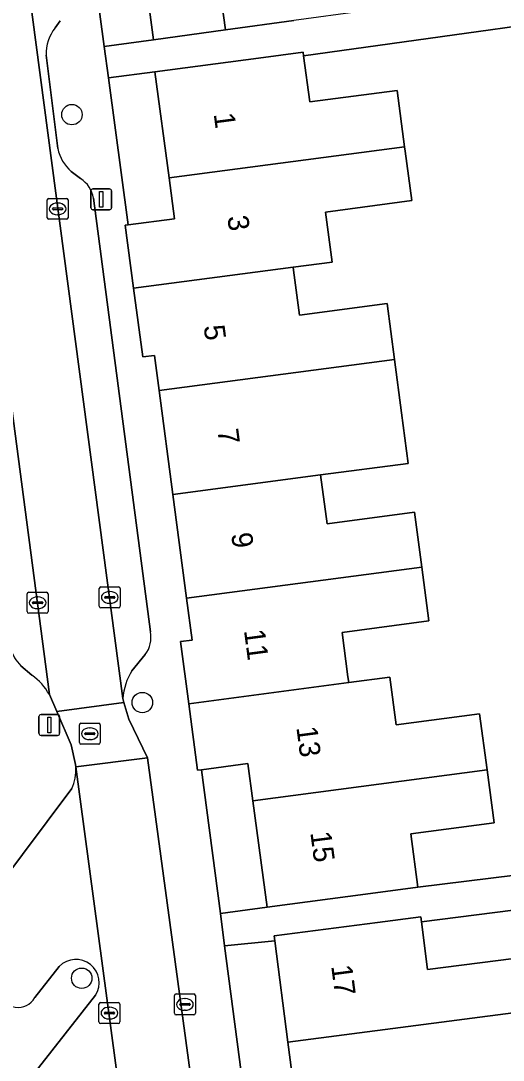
# Model space of a CAD drawing. Extents: x 163147 to 163550, y 380933 to 381639.
# Drawn here: x 163326.27 to 163349.36, y 381413.54 to 381463.34 of the extents above; entities that cross this region are included whole.
import ezdxf

# ---------------------------------------------------------------- set-up
doc = ezdxf.new("R2010")
doc.units = 0
for name, color, linetype in [('IMGEO_Boom', 7, 'Continuous'), ('IMGEO_Erf', 7, 'Continuous'), ('IMGEO_Kolk', 7, 'Continuous'), ('IMGEO_Lichtmast', 7, 'Continuous'), ('IMGEO_Pand', 7, 'Continuous'), ('IMGEO_Pand_nummerreeks', 7, 'Continuous'), ('IMGEO_Parkeervlak_open', 7, 'Continuous'), ('IMGEO_Rijbaan_lokaal_open', 7, 'Continuous'), ('IMGEO_Rioolput', 7, 'Continuous'), ('IMGEO_Voetpad_open', 7, 'Continuous')]:
    doc.layers.add(name, color=color, linetype=linetype)

msp = doc.modelspace()

# ---------------------------------------------------------------- linework, layer by layer
at = {"layer": 'IMGEO_Boom'}
for centre in [(163328.72, 381458.839), (163332.089, 381430.675), (163329.187, 381417.469)]:
    msp.add_circle(centre, 0.489, dxfattribs=at)
at = {"layer": 'IMGEO_Erf'}
for points in [[(163327.51, 381482.721), (163330.269, 381462.107), (163332.631, 381462.423), (163332.25, 381465.197)], [(163335.686, 381465.67), (163336.067, 381462.896), (163339.339, 381463.347)], [(163358.388, 381464.242), (163339.808, 381461.652), (163340.1, 381459.446), (163344.282, 381460), (163344.64, 381457.298), (163344.668, 381457.09), (163344.982, 381454.719), (163340.863, 381454.173), (163341.181, 381451.778), (163339.303, 381451.53), (163339.322, 381451.385), (163339.607, 381449.237), (163343.805, 381449.793), (163344.16, 381447.11), (163344.498, 381444.558), (163344.819, 381442.134), (163340.621, 381441.579), (163340.931, 381439.239), (163345.113, 381439.793), (163345.462, 381437.157), (163345.803, 381434.582), (163341.649, 381434.032), (163341.93, 381431.91), (163341.967, 381431.632), (163343.93, 381431.892), (163344.231, 381429.611), (163348.23, 381430.14), (163348.587, 381427.446), (163348.922, 381424.915), (163344.932, 381424.387), (163345.271, 381421.825), (163364.034, 381424.153)], [(163365.447, 381412.799), (163365.299, 381413.897), (163365.397, 381413.911), (163365.319, 381414.45), (163361.948, 381413.958), (163361.457, 381417.324), (163360.95, 381420.808), (163364.321, 381421.299), (163364.137, 381422.557), (163345.444, 381420.177), (163345.743, 381417.879), (163349.875, 381418.417), (163350.208, 381415.86), (163350.548, 381413.245)]]:
    msp.add_lwpolyline(points, dxfattribs=at)
for points in [[(163332.691, 381460.898), (163330.47, 381460.601), (163331.412, 381453.563), (163333.624, 381453.855), (163333.366, 381455.806)], [(163337.382, 381425.964), (163337.146, 381427.749), (163334.918, 381427.453), (163335.823, 381420.576), (163338.057, 381420.87)], [(163341.643, 381394.54), (163340.996, 381399.507), (163340.35, 381404.474), (163339.703, 381409.442), (163339.057, 381414.409), (163338.425, 381419.264), (163336.029, 381419.012), (163342.573, 381369.282), (163344.89, 381369.587), (163344.228, 381374.671), (163343.582, 381379.638), (163342.936, 381384.606), (163342.289, 381389.573)]]:
    msp.add_lwpolyline(points, close=True, dxfattribs=at)
at = {"layer": 'IMGEO_Kolk'}
for p, q in [((163327.536, 381453.899), (163327.536, 381454.751)), ((163327.611, 381454.825), (163328.463, 381454.825)), ((163328.024, 381454.605), (163328.049, 381454.605)), ((163328.537, 381454.751), (163328.537, 381453.899)), ((163327.795, 381454.319), (163327.795, 381454.331)), ((163328.233, 381454.282), (163327.835, 381454.282)), ((163327.838, 381454.368), (163328.236, 381454.368)), ((163328.047, 381454.045), (163328.022, 381454.045)), ((163328.279, 381454.331), (163328.279, 381454.319)), ((163328.463, 381453.825), (163327.611, 381453.825)), ((163326.653, 381435.956), (163327.505, 381435.956)), ((163330.028, 381435.285), (163330.028, 381436.137)), ((163330.103, 381436.211), (163330.955, 381436.211)), ((163330.516, 381435.991), (163330.541, 381435.991)), ((163331.029, 381436.137), (163331.029, 381435.285)), ((163326.578, 381435.03), (163326.578, 381435.882)), ((163326.837, 381435.45), (163326.837, 381435.462)), ((163326.88, 381435.499), (163327.278, 381435.499)), ((163327.066, 381435.736), (163327.091, 381435.736)), ((163327.321, 381435.462), (163327.321, 381435.45)), ((163327.579, 381435.882), (163327.579, 381435.03)), ((163330.287, 381435.705), (163330.287, 381435.717)), ((163330.725, 381435.668), (163330.327, 381435.668)), ((163330.33, 381435.754), (163330.728, 381435.754)), ((163330.771, 381435.717), (163330.771, 381435.705)), ((163327.275, 381435.413), (163326.877, 381435.413)), ((163327.089, 381435.176), (163327.064, 381435.176)), ((163330.955, 381435.211), (163330.103, 381435.211)), ((163330.539, 381435.431), (163330.514, 381435.431)), ((163327.505, 381434.956), (163326.653, 381434.956)), ((163333.628, 381415.788), (163333.628, 381416.64)), ((163333.703, 381416.714), (163334.555, 381416.714)), ((163334.629, 381416.64), (163334.629, 381415.788)), ((163330.012, 381415.373), (163330.012, 381416.225)), ((163330.087, 381416.299), (163330.939, 381416.299)), ((163330.5, 381416.079), (163330.525, 381416.079)), ((163331.013, 381416.225), (163331.013, 381415.373)), ((163333.887, 381416.208), (163333.887, 381416.22)), ((163334.325, 381416.171), (163333.927, 381416.171)), ((163333.93, 381416.257), (163334.328, 381416.257)), ((163334.116, 381416.494), (163334.141, 381416.494)), ((163334.371, 381416.22), (163334.371, 381416.208)), ((163330.271, 381415.793), (163330.271, 381415.805)), ((163330.709, 381415.756), (163330.311, 381415.756)), ((163330.314, 381415.842), (163330.712, 381415.842)), ((163330.755, 381415.805), (163330.755, 381415.793)), ((163334.555, 381415.714), (163333.703, 381415.714)), ((163334.139, 381415.934), (163334.114, 381415.934)), ((163330.939, 381415.299), (163330.087, 381415.299)), ((163330.523, 381415.519), (163330.498, 381415.519))]:
    msp.add_line(p, q, dxfattribs=at)
for points in [[(163327.536, 381453.899), (163327.536, 381454.751)], [(163327.611, 381454.825), (163328.463, 381454.825)], [(163328.537, 381454.751), (163328.537, 381453.899)], [(163328.463, 381453.825), (163327.611, 381453.825)], [(163326.653, 381435.956), (163327.505, 381435.956)], [(163330.028, 381435.285), (163330.028, 381436.137)], [(163330.103, 381436.211), (163330.955, 381436.211)], [(163331.029, 381436.137), (163331.029, 381435.285)], [(163326.578, 381435.03), (163326.578, 381435.882)], [(163327.579, 381435.882), (163327.579, 381435.03)], [(163330.955, 381435.211), (163330.103, 381435.211)], [(163327.505, 381434.956), (163326.653, 381434.956)], [(163333.628, 381415.788), (163333.628, 381416.64)], [(163333.703, 381416.714), (163334.555, 381416.714)], [(163334.629, 381416.64), (163334.629, 381415.788)], [(163330.012, 381415.373), (163330.012, 381416.225)], [(163330.087, 381416.299), (163330.939, 381416.299)], [(163331.013, 381416.225), (163331.013, 381415.373)], [(163334.555, 381415.714), (163333.703, 381415.714)], [(163330.939, 381415.299), (163330.087, 381415.299)]]:
    msp.add_lwpolyline(points, dxfattribs=at)
for centre, radius, start, end in [((163327.613, 381454.749), 0.0765, 91.552, 178.448), ((163327.613, 381454.749), 0.0765, 91.552, 178.448), ((163328.461, 381454.749), 0.0765, 1.552, 88.448), ((163328.461, 381454.749), 0.0765, 1.552, 88.448), ((163327.613, 381453.901), 0.0765, 181.552, 268.448), ((163327.613, 381453.901), 0.0765, 181.552, 268.448), ((163327.835, 381454.328), 0.0403, 85.8775, 175.7526), ((163327.832, 381454.318), 0.0366, 178.938, 274.7102), ((163328.236, 381454.325), 0.043, 264.8664, 352.4533), ((163328.24, 381454.33), 0.0386, 1.7309, 96.639), ((163328.461, 381453.901), 0.0765, 271.552, 358.448), ((163328.461, 381453.901), 0.0765, 271.552, 358.448), ((163326.655, 381435.88), 0.0765, 91.552, 178.448), ((163326.655, 381435.88), 0.0765, 91.552, 178.448), ((163327.503, 381435.88), 0.0765, 1.552, 88.448), ((163327.503, 381435.88), 0.0765, 1.552, 88.448), ((163330.105, 381436.135), 0.0765, 91.552, 178.448), ((163330.105, 381436.135), 0.0765, 91.552, 178.448), ((163330.953, 381436.135), 0.0765, 1.552, 88.448), ((163330.953, 381436.135), 0.0765, 1.552, 88.448), ((163326.877, 381435.459), 0.0403, 85.8775, 175.7526), ((163327.282, 381435.461), 0.0386, 1.7309, 96.639), ((163330.327, 381435.714), 0.0403, 85.8775, 175.7526), ((163330.324, 381435.704), 0.0366, 178.938, 274.7102), ((163330.728, 381435.711), 0.043, 264.8664, 352.4533), ((163330.732, 381435.716), 0.0386, 1.7309, 96.639), ((163326.655, 381435.032), 0.0765, 181.552, 268.448), ((163326.655, 381435.032), 0.0765, 181.552, 268.448), ((163326.874, 381435.449), 0.0366, 178.938, 274.7102), ((163327.278, 381435.456), 0.043, 264.8664, 352.4533), ((163327.503, 381435.032), 0.0765, 271.552, 358.448), ((163327.503, 381435.032), 0.0765, 271.552, 358.448), ((163330.105, 381435.287), 0.0765, 181.552, 268.448), ((163330.105, 381435.287), 0.0765, 181.552, 268.448), ((163330.953, 381435.287), 0.0765, 271.552, 358.448), ((163330.953, 381435.287), 0.0765, 271.552, 358.448), ((163333.705, 381416.638), 0.0765, 91.552, 178.448), ((163333.705, 381416.638), 0.0765, 91.552, 178.448), ((163334.553, 381416.638), 0.0765, 1.552, 88.448), ((163334.553, 381416.638), 0.0765, 1.552, 88.448), ((163330.089, 381416.223), 0.0765, 91.552, 178.448), ((163330.089, 381416.223), 0.0765, 91.552, 178.448), ((163330.937, 381416.223), 0.0765, 1.552, 88.448), ((163330.937, 381416.223), 0.0765, 1.552, 88.448), ((163333.927, 381416.217), 0.0403, 85.8775, 175.7526), ((163333.924, 381416.207), 0.0366, 178.938, 274.7102), ((163334.328, 381416.214), 0.043, 264.8664, 352.4533), ((163334.332, 381416.219), 0.0386, 1.7309, 96.639), ((163330.311, 381415.802), 0.0403, 85.8775, 175.7526), ((163330.308, 381415.792), 0.0366, 178.938, 274.7102), ((163330.712, 381415.799), 0.043, 264.8664, 352.4533), ((163330.716, 381415.804), 0.0386, 1.7309, 96.639), ((163333.705, 381415.79), 0.0765, 181.552, 268.448), ((163333.705, 381415.79), 0.0765, 181.552, 268.448), ((163334.553, 381415.79), 0.0765, 271.552, 358.448), ((163334.553, 381415.79), 0.0765, 271.552, 358.448), ((163330.089, 381415.375), 0.0765, 181.552, 268.448), ((163330.089, 381415.375), 0.0765, 181.552, 268.448), ((163330.937, 381415.375), 0.0765, 271.552, 358.448), ((163330.937, 381415.375), 0.0765, 271.552, 358.448)]:
    msp.add_arc(centre, radius, start, end, dxfattribs=at)
for centre, major_axis, ratio, start_param, end_param in [((163328.023, 381454.325), (-0.387, 0.002), 0.722429, 4.712389, 7.853982), ((163328.048, 381454.325), (-0.39, 0.002), 0.717154, 1.570796, 4.712389), ((163330.515, 381435.711), (-0.387, 0.002), 0.722429, 4.712389, 7.853982), ((163330.54, 381435.711), (-0.39, 0.002), 0.717154, 1.570796, 4.712389), ((163327.065, 381435.456), (-0.387, 0.002), 0.722429, 4.712389, 7.853982), ((163327.09, 381435.456), (-0.39, 0.002), 0.717154, 1.570796, 4.712389), ((163330.499, 381415.799), (-0.387, 0.002), 0.722429, 4.712389, 7.853982), ((163330.524, 381415.799), (-0.39, 0.002), 0.717154, 1.570796, 4.712389), ((163334.115, 381416.214), (-0.387, 0.002), 0.722429, 4.712389, 7.853982), ((163334.14, 381416.214), (-0.39, 0.002), 0.717154, 1.570796, 4.712389)]:
    msp.add_ellipse(centre, major_axis=major_axis, ratio=ratio, start_param=start_param, end_param=end_param, dxfattribs=at)
at = {"layer": 'IMGEO_Lichtmast'}
for p, q in [((163329.626, 381454.382), (163329.626, 381455.182)), ((163329.626, 381455.182), (163329.626, 381454.382)), ((163329.726, 381455.282), (163330.516, 381455.282)), ((163330.516, 381455.282), (163329.726, 381455.282)), ((163330.616, 381455.182), (163330.616, 381454.382)), ((163330.616, 381454.382), (163330.616, 381455.182)), ((163330.516, 381454.282), (163329.726, 381454.282)), ((163329.726, 381454.282), (163330.516, 381454.282)), ((163327.141, 381429.202), (163327.141, 381430.002)), ((163327.141, 381430.002), (163327.141, 381429.202)), ((163327.241, 381430.102), (163328.031, 381430.102)), ((163328.031, 381430.102), (163327.241, 381430.102)), ((163328.131, 381430.002), (163328.131, 381429.202)), ((163328.131, 381429.202), (163328.131, 381430.002)), ((163328.031, 381429.102), (163327.241, 381429.102)), ((163327.241, 381429.102), (163328.031, 381429.102))]:
    msp.add_line(p, q, dxfattribs=at)
for points in [[(163330.046, 381455.157), (163330.196, 381455.157), (163330.196, 381454.407), (163330.046, 381454.407), (163330.046, 381455.157)], [(163327.561, 381429.977), (163327.711, 381429.977), (163327.711, 381429.227), (163327.561, 381429.227), (163327.561, 381429.977)]]:
    msp.add_lwpolyline(points, dxfattribs=at)
for centre, start, end in [((163329.726, 381455.182), 90, 180), ((163329.726, 381455.182), 90, 180), ((163330.516, 381455.182), 0, 90), ((163330.516, 381455.182), 360, 90), ((163329.726, 381454.382), 180, 270), ((163329.726, 381454.382), 180, 270), ((163330.516, 381454.382), 270, 0), ((163330.516, 381454.382), 270, 0), ((163327.241, 381430.002), 90, 180), ((163327.241, 381430.002), 90, 180), ((163328.031, 381430.002), 0, 90), ((163328.031, 381430.002), 360, 90), ((163327.241, 381429.202), 180, 270), ((163327.241, 381429.202), 180, 270), ((163328.031, 381429.202), 270, 0), ((163328.031, 381429.202), 270, 0)]:
    msp.add_arc(centre, 0.1, start, end, dxfattribs=at)
at = {"layer": 'IMGEO_Pand'}
for points in [[(163332.631, 381462.423), (163336.067, 381462.896), (163335.686, 381465.67), (163332.25, 381465.197)], [(163339.808, 381461.652), (163339.783, 381461.837), (163337.642, 381461.553), (163332.691, 381460.898), (163333.366, 381455.806), (163344.64, 381457.298), (163344.282, 381460), (163340.1, 381459.446)], [(163344.982, 381454.719), (163344.668, 381457.09), (163344.64, 381457.298), (163333.366, 381455.806), (163333.624, 381453.855), (163331.412, 381453.563), (163331.272, 381453.544), (163331.672, 381450.52), (163339.303, 381451.53), (163341.181, 381451.778), (163340.863, 381454.173)], [(163343.805, 381449.793), (163339.607, 381449.237), (163339.322, 381451.385), (163339.303, 381451.53), (163331.672, 381450.52), (163332.108, 381447.23), (163332.664, 381447.303), (163332.887, 381445.619), (163344.16, 381447.11)], [(163333.546, 381440.643), (163340.621, 381441.579), (163344.819, 381442.134), (163344.498, 381444.558), (163344.16, 381447.11), (163332.887, 381445.619)], [(163334.204, 381435.668), (163345.462, 381437.157), (163345.113, 381439.793), (163340.931, 381439.239), (163340.621, 381441.579), (163333.546, 381440.643)], [(163341.649, 381434.032), (163345.803, 381434.582), (163345.462, 381437.157), (163334.204, 381435.668), (163334.469, 381433.668), (163333.918, 381433.595), (163334.312, 381430.619), (163341.967, 381431.632), (163341.93, 381431.91)], [(163348.23, 381430.14), (163344.231, 381429.611), (163343.93, 381431.892), (163341.967, 381431.632), (163334.312, 381430.619), (163334.735, 381427.429), (163334.918, 381427.453), (163337.146, 381427.749), (163337.382, 381425.964), (163348.587, 381427.446)], [(163337.382, 381425.964), (163338.057, 381420.87), (163343.014, 381421.526), (163345.271, 381421.825), (163344.932, 381424.387), (163348.922, 381424.915), (163348.587, 381427.446)], [(163345.444, 381420.177), (163345.414, 381420.41), (163343.349, 381420.141), (163338.395, 381419.497), (163338.425, 381419.264), (163339.057, 381414.409), (163350.208, 381415.86), (163349.875, 381418.417), (163345.743, 381417.879)], [(163339.703, 381409.442), (163346.781, 381410.363), (163346.475, 381412.715), (163350.548, 381413.245), (163350.208, 381415.86), (163339.057, 381414.409)]]:
    msp.add_lwpolyline(points, close=True, dxfattribs=at)
at = {"layer": 'IMGEO_Parkeervlak_open'}
for points in [[(163325.105, 381476.415), (163331.157, 381430.873)], [(163327.639, 381431.061), (163321.781, 381475.592)], [(163327.918, 381462.994), (163328.161, 381463.336)], [(163328.045, 381457.216), (163327.481, 381461.688)], [(163329.131, 381455.777), (163328.688, 381456.121)], [(163332.477, 381434.063), (163329.749, 381454.834)], [(163331.593, 381432.2), (163332.231, 381432.972)], [(163326.273, 381432.439), (163326.805, 381431.98)], [(163337.636, 381362.402), (163328.901, 381427.589)], [(163328.711, 381426.55), (163325.16, 381421.816)], [(163326.94, 381416.539), (163328.115, 381418.032)], [(163329.849, 381416.653), (163326.299, 381412.136)]]:
    msp.add_lwpolyline(points, dxfattribs=at)
for centre, radius, start, end in [((163329.424, 381461.764), 1.944, 140.7576, 182.2409), ((163329.961, 381457.605), 1.955, 191.467, 229.3772), ((163328.412, 381454.632), 1.352, 8.5937, 57.8844), ((163331.094, 381433.802), 1.408, 323.886, 10.7008), ((163327.687, 381433.838), 1.989, 196.7102, 224.6861), ((163325.204, 381429.689), 2.795, 29.3956, 55.0524), ((163334.023, 381430.667), 2.873, 147.7432, 175.8798), ((163326.943, 381427.41), 1.966, 334.0524, 5.2215), ((163328.91, 381417.251), 1.114, 327.5064, 135.5052), ((163326.137, 381416.982), 0.917, 192.1867, 331.1475)]:
    msp.add_arc(centre, radius, start, end, dxfattribs=at)
at = {"layer": 'IMGEO_Rijbaan_lokaal_open'}
for points in [[(163325.105, 381476.415), (163324.774, 381478.904), (163321.405, 381478.446), (163321.781, 381475.592), (163327.639, 381431.061), (163327.996, 381430.242), (163331.211, 381430.682), (163331.157, 381430.873)], [(163331.211, 381430.682), (163327.996, 381430.242), (163328.69, 381428.651), (163328.886, 381427.703), (163328.901, 381427.589), (163332.34, 381428.031), (163331.438, 381429.883)], [(163337.636, 381362.402), (163337.687, 381362.02), (163337.718, 381361.47), (163337.698, 381361.35), (163340.886, 381361.766), (163341.054, 381362.862), (163341.003, 381364.082), (163332.34, 381428.031), (163328.901, 381427.589)]]:
    msp.add_lwpolyline(points, close=True, dxfattribs=at)
at = {"layer": 'IMGEO_Rioolput'}
for p, q in [((163329.076, 381428.754), (163329.076, 381429.606)), ((163329.151, 381429.68), (163330.003, 381429.68)), ((163330.077, 381429.606), (163330.077, 381428.754)), ((163329.335, 381429.174), (163329.335, 381429.186)), ((163329.773, 381429.137), (163329.375, 381429.137)), ((163329.378, 381429.223), (163329.776, 381429.223)), ((163329.564, 381429.46), (163329.589, 381429.46)), ((163329.819, 381429.186), (163329.819, 381429.174)), ((163330.003, 381428.68), (163329.151, 381428.68)), ((163329.587, 381428.9), (163329.562, 381428.9))]:
    msp.add_line(p, q, dxfattribs=at)
for points in [[(163329.076, 381428.754), (163329.076, 381429.606)], [(163329.151, 381429.68), (163330.003, 381429.68)], [(163330.077, 381429.606), (163330.077, 381428.754)], [(163330.003, 381428.68), (163329.151, 381428.68)]]:
    msp.add_lwpolyline(points, dxfattribs=at)
for centre, radius, start, end in [((163329.153, 381429.604), 0.0765, 91.552, 178.448), ((163329.153, 381429.604), 0.0765, 91.552, 178.448), ((163330.001, 381429.604), 0.0765, 1.552, 88.448), ((163330.001, 381429.604), 0.0765, 1.552, 88.448), ((163329.375, 381429.183), 0.0403, 85.8775, 175.7526), ((163329.372, 381429.173), 0.0366, 178.938, 274.7102), ((163329.776, 381429.18), 0.043, 264.8664, 352.4533), ((163329.78, 381429.185), 0.0386, 1.7309, 96.639), ((163329.153, 381428.756), 0.0765, 181.552, 268.448), ((163329.153, 381428.756), 0.0765, 181.552, 268.448), ((163330.001, 381428.756), 0.0765, 271.552, 358.448), ((163330.001, 381428.756), 0.0765, 271.552, 358.448)]:
    msp.add_arc(centre, radius, start, end, dxfattribs=at)
for centre, major_axis, ratio, start_param, end_param in [((163329.563, 381429.18), (-0.387, 0.002), 0.722429, 4.712389, 7.853982), ((163329.588, 381429.18), (-0.39, 0.002), 0.717154, 1.570796, 4.712389)]:
    msp.add_ellipse(centre, major_axis=major_axis, ratio=ratio, start_param=start_param, end_param=end_param, dxfattribs=at)
at = {"layer": 'IMGEO_Voetpad_open'}
for points in [[(163342.573, 381369.282), (163336.029, 381419.012), (163335.823, 381420.576), (163334.918, 381427.453), (163334.735, 381427.429), (163334.312, 381430.619), (163333.918, 381433.595), (163334.469, 381433.668), (163334.204, 381435.668), (163333.546, 381440.643), (163332.887, 381445.619), (163332.664, 381447.303), (163332.108, 381447.23), (163331.672, 381450.52), (163331.272, 381453.544), (163331.412, 381453.563), (163330.47, 381460.601), (163330.269, 381462.107), (163327.51, 381482.721)], [(163352.538, 381465.163), (163348.878, 381464.66), (163346.334, 381464.309), (163342.649, 381463.802), (163339.339, 381463.347), (163336.067, 381462.896), (163332.631, 381462.423), (163330.269, 381462.107), (163330.47, 381460.601), (163332.691, 381460.898), (163337.642, 381461.553), (163339.783, 381461.837), (163339.808, 381461.652), (163358.388, 381464.242)], [(163328.161, 381463.336), (163327.918, 381462.994)], [(163327.481, 381461.688), (163328.045, 381457.216)], [(163328.688, 381456.121), (163329.131, 381455.777)], [(163329.749, 381454.834), (163332.477, 381434.063)], [(163332.231, 381432.972), (163331.593, 381432.2)], [(163326.805, 381431.98), (163326.273, 381432.439)], [(163328.901, 381427.589), (163328.886, 381427.703), (163328.69, 381428.651), (163327.996, 381430.242), (163327.639, 381431.061)], [(163331.157, 381430.873), (163331.211, 381430.682), (163331.438, 381429.883), (163332.34, 381428.031), (163341.003, 381364.082), (163341.054, 381362.862), (163340.886, 381361.766), (163340.657, 381360.272), (163341.137, 381359.042), (163341.822, 381358.499), (163342.151, 381358.294)], [(163325.16, 381421.816), (163328.711, 381426.55)], [(163364.034, 381424.153), (163345.271, 381421.825), (163343.014, 381421.526), (163338.057, 381420.87), (163335.823, 381420.576), (163336.029, 381419.012), (163338.425, 381419.264), (163338.395, 381419.497), (163343.349, 381420.141), (163345.414, 381420.41), (163345.444, 381420.177), (163364.137, 381422.557)], [(163328.115, 381418.032), (163326.94, 381416.539)], [(163326.299, 381412.136), (163329.849, 381416.653)]]:
    msp.add_lwpolyline(points, dxfattribs=at)
for centre, radius, start, end in [((163329.424, 381461.764), 1.944, 140.7576, 182.2409), ((163329.961, 381457.605), 1.955, 191.467, 229.3772), ((163328.412, 381454.632), 1.352, 8.5937, 57.8844), ((163331.094, 381433.802), 1.408, 323.886, 10.7008), ((163327.687, 381433.838), 1.989, 196.7102, 224.6861), ((163325.204, 381429.689), 2.795, 29.3956, 55.0524), ((163334.023, 381430.667), 2.873, 147.7432, 175.8798), ((163326.943, 381427.41), 1.966, 334.0524, 5.2215), ((163328.91, 381417.251), 1.114, 327.5064, 135.5052), ((163326.137, 381416.982), 0.917, 192.1867, 331.1475)]:
    msp.add_arc(centre, radius, start, end, dxfattribs=at)

# ---------------------------------------------------------------- texts
at = {"layer": 'IMGEO_Pand_nummerreeks'}
for s, rotation, p in [('1', 277.5456, (163335.502, 381458.873)), ('3', 277.5456, (163336.154, 381453.953)), ('5', 277.5399, (163335.021, 381448.709)), ('7', 277.541, (163335.678, 381443.734)), ('9', 277.541, (163336.337, 381438.759)), ('11', 277.5399, (163336.951, 381434.128)), ('13', 277.5456, (163339.459, 381429.481)), ('15', 277.5439, (163340.126, 381424.447)), ('17', 277.4139, (163341.125, 381418.056))]:
    msp.add_text(s, height=1, rotation=rotation, dxfattribs=at).set_placement(p)

doc.saveas('drawing.dxf')
